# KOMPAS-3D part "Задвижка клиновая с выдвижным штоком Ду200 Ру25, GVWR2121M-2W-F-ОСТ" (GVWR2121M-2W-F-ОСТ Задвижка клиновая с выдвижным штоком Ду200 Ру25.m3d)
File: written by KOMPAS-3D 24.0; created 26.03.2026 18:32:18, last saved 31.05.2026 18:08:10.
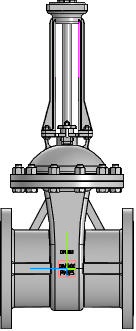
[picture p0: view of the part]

Document properties: Автор: R2D2; Полное имя файла: E:\Работа\Зайцев\GVWR2121M-2W-F-ОСТ Задвижка клиновая 30с964нж DN.ru Ду50-300 Ру25\исходные материалы\DN200\GVWR2121M-2W-F-ОСТ Задвижка клиновая с выдвижным штоком Ду200 Ру25.m3d

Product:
- Component [detail]: AS 1110 - M10 x 35  | qty 4  | pos. 2  | Комментарий: Болты и винты   шестигранные точные   метрические ISO; Автор: R2D2; additional columns: Сталь, мягкая; source file: AS 1110 - M10 x 35 AS 1110 - M10 x 35.m3d
- Component [detail]: ANSI B18.2.4.2M - M10x1,5 - 16  | designation ANSI B18.2.4.2M - M10x1,5  | qty 4  | pos. 3  | Комментарий: Типы метрических   шестигранных гаек   2; Автор: R2D2; additional columns: Сталь, мягкая; source file: ANSI B18.2.4.2M - M10x1,5 ANSI B18.2.4.2M - M10x1,5 - 16.m3d
- Component [detail]: ANSI B18.2.4.2M - M8x1,25 - 13  | designation ANSI B18.2.4.2M - M8x1,25  | qty 1  | pos. 4  | Комментарий: Типы метрических   шестигранных гаек   2; Автор: R2D2; additional columns: Сталь, мягкая; source file: ANSI B18.2.4.2M - M8x1,25 ANSI B18.2.4.2M - M8x1,25 - 13.m3d
- Component [detail]: ANSI B18.2.4.2M - M20x2,5 - 30  | designation ANSI B18.2.4.2M - M20x2,5  | qty 12  | pos. 5  | Комментарий: Типы метрических   шестигранных гаек   2; Автор: R2D2; additional columns: Сталь, мягкая; source file: ANSI B18.2.4.2M - M20x2,5 ANSI B18.2.4.2M - M20x2,5 - 30.m3d
- Component [detail]: AS 1110 - M20 x 70  | qty 12  | pos. 6  | Комментарий: Болты и винты   шестигранные точные   метрические ISO; Автор: R2D2; additional columns: Сталь, мягкая; source file: AS 1110 - M20 x 70 AS 1110 - M20 x 70.m3d
- Component [detail]: Деталь1  | qty 1  | pos. 7  | Автор: R2D2; additional columns: Типовые; source file: 2.m3d
- Component [detail]: ANSI B18.2.4.2M - M8x1,25 - 13  | designation ANSI B18.2.4.2M - M8x1,25-01  | qty 1  | pos. 8  | Комментарий: Типы метрических   шестигранных гаек   2; Автор: R2D2; additional columns: Сталь, мягкая; source file: ANSI B18.2.4.2M - M8x1,25 ANSI B18.2.4.2M - M8x1,25 - 13.m3d
- Component [detail]: Фланец  | qty 2  | pos. 7  | Автор: R2D2; additional columns: Типовые; source file: Фланец DN200 Pn25 b34.m3d
- Component [detail]: Деталь1  | qty 1  | pos. 9  | Автор: R2D2; additional columns: Типовые; source file: Фланец Б.m3d
- Body: Тело 1  | qty 1
    Масса: 185.039352
- Body: Тело 2  | qty 1
    Масса: 185.039352
- Part/product: Задвижка клиновая с выдвижным штоком Ду200 Ру25  | designation GVWR2121M-2W-F-ОСТ
    Масса: 130
    Раздел спецификации: Прочие изделия
    Примечание: D040-09832

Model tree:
1. Массив по концентрической сетке:1  (labels: Грань.Твердое тело1)  (12 pattern instances)
     Шаг 2 = 360
2. Массив по сетке:1  (labels: Грань.Твердое тело1)  (4 pattern instances)
     Шаг 1 = 50; Угол раствора = 90; Шаг 2 = 120
3. Масштабирование:1
4. Масштабирование : Твердое тело1
5. Масштабирование : Solid1
6. Масштабирование : Ребро.Solid1  (with: Масштабирование : Solid1)  (labels: Твердое тело1; Solid1; Ребро.Solid1)
     Масштаб по оси Х = 1; Масштаб по оси Y = 1; Масштаб по оси Z = 1; Коэффициент = 1.25
7. Элемент выдавливания:1  (with: Грань.Элемент выдавливания:2, Грань.Элемент вращения:1)
     Расстояние 1 = 33.5965
8. Элемент выдавливания:2  (with: Грань.Элемент выдавливания:1, Грань.Элемент вращения:1)
     Расстояние 1 = 40.4417
9. Скругление:1  (with: Ребро.Элемент выдавливания:2, Ребро.Элемент выдавливания:1)
     Радиус = 10
10. Элемент выдавливания:3  (with: Грань.Элемент выдавливания:1)
     Расстояние 1 = 70
11. Эскиз:1  (with: Вершина.Элемент выдавливания:3)
12. Элемент выдавливания:4  (with: Грань.Элемент выдавливания:1, Грань.Элемент выдавливания:4)
     Расстояние 1 = 291.906
13. Эскиз:2
14. Элемент выдавливания:5  (with: Грань.Элемент выдавливания:1)
     Расстояние 1 = 126; Смещение 1 = 1
15. Элемент по траектории:2  (with: Грань.Элемент выдавливания:3, Грань.Элемент вращения:1)  (labels: Грань.Твердое тело1; Грань.Solid1; Solid1; Твердое тело1)
     Длина траектории = 397.552; Ориентация = 2; Расстояние = -200; Ориентация = 2; Расстояние = -800

Referenced files in E:\Работа\Зайцев\GVWR2121M-2W-F-ОСТ Задвижка клиновая 30с964нж DN.ru Ду50-300 Ру25\исходные материалы\DN200\: AS 1110 - M10 x 35 AS 1110 - M10 x 35.m3d, ANSI B18.2.4.2M - M10x1,5 ANSI B18.2.4.2M - M10x1,5 - 16.m3d, ANSI B18.2.4.2M - M8x1,25 ANSI B18.2.4.2M - M8x1,25 - 13.m3d, ANSI B18.2.4.2M - M20x2,5 ANSI B18.2.4.2M - M20x2,5 - 30.m3d, AS 1110 - M20 x 70 AS 1110 - M20 x 70.m3d, 2.m3d, Фланец Б.m3d, Фланец DN200 Pn25 b34.m3d
Referenced files in E:\Работа\Зайцев\GVWR3131M-2W-F-S Задвижка клиновая с выдвижным штоком DN.ru Ду50-200 Ру63\DN200\исходные материалы\: ANSI B18.2.4.2M - M20x2,5 ANSI B18.2.4.2M - M20x2,5 - 30.m3d, AS 1110 - M20 x 70 AS 1110 - M20 x 70.m3d, ANSI B18.2.4.2M - M10x1,5 ANSI B18.2.4.2M - M10x1,5 - 16.m3d, AS 1110 - M10 x 35 AS 1110 - M10 x 35.m3d
Referenced files in E:\Работа\Зайцев\GVWR2434M-2W-F-ОСТ Задвижка клиновая с выдвижным штоком DN.ru Ду50-300 Ру25\исходные материалы\DN200\: Фланец DN200 Pn25 b34.m3d
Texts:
  GVWR2121M-2W-F-ОСТ
  DN200
  GOST 26.020 Pr3
  PN25
  AS 1110 - M10 x 35 AS 1110 - M10 x 35 (1)
  ANSI B18.2.4.2M - M10x1,5 ANSI B18.2.4.2M - M10x1,5 - 16 (1)
  ANSI B18.2.4.2M - M8x1,25 ANSI B18.2.4.2M - M8x1,25 - 13
  ANSI B18.2.4.2M - M20x2,5 ANSI B18.2.4.2M - M20x2,5 - 30 (1)
  AS 1110 - M20 x 70 AS 1110 - M20 x 70 (1)
  Деталь1 Деталь1
  ANSI B18.2.4.2M - M8x1,25-01 ANSI B18.2.4.2M - M8x1,25 - 13
  Фланец (1)
  Фланец (2)
  Ось Y.Начало координат
  Ось Z.Начало координат
  Плоскость ZY.Начало координат
  Плоскость ZX.Начало координат
  Плоскость XY.Начало координат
